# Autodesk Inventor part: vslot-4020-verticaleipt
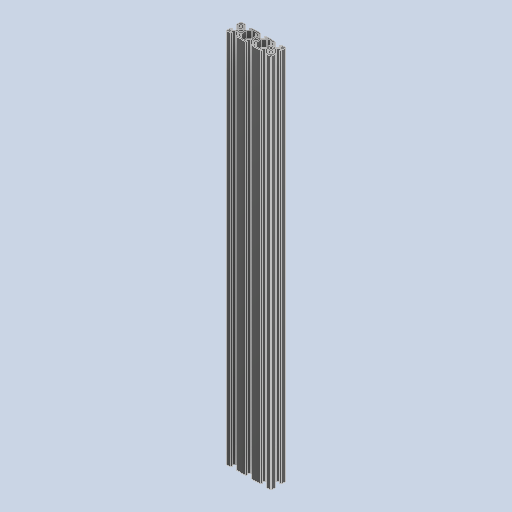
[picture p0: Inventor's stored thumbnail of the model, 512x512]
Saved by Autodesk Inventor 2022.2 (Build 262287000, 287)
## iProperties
Created: 2024-10
Part Number: vslot-4020-verticaleipt
Material: Generico
Document SubType Name: Modeling
Designer: 18907419
Density: 1 g/cm^3
Appearance: Default
Author: 18907419
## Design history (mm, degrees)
feature "Solido47"
node "Solido1"
